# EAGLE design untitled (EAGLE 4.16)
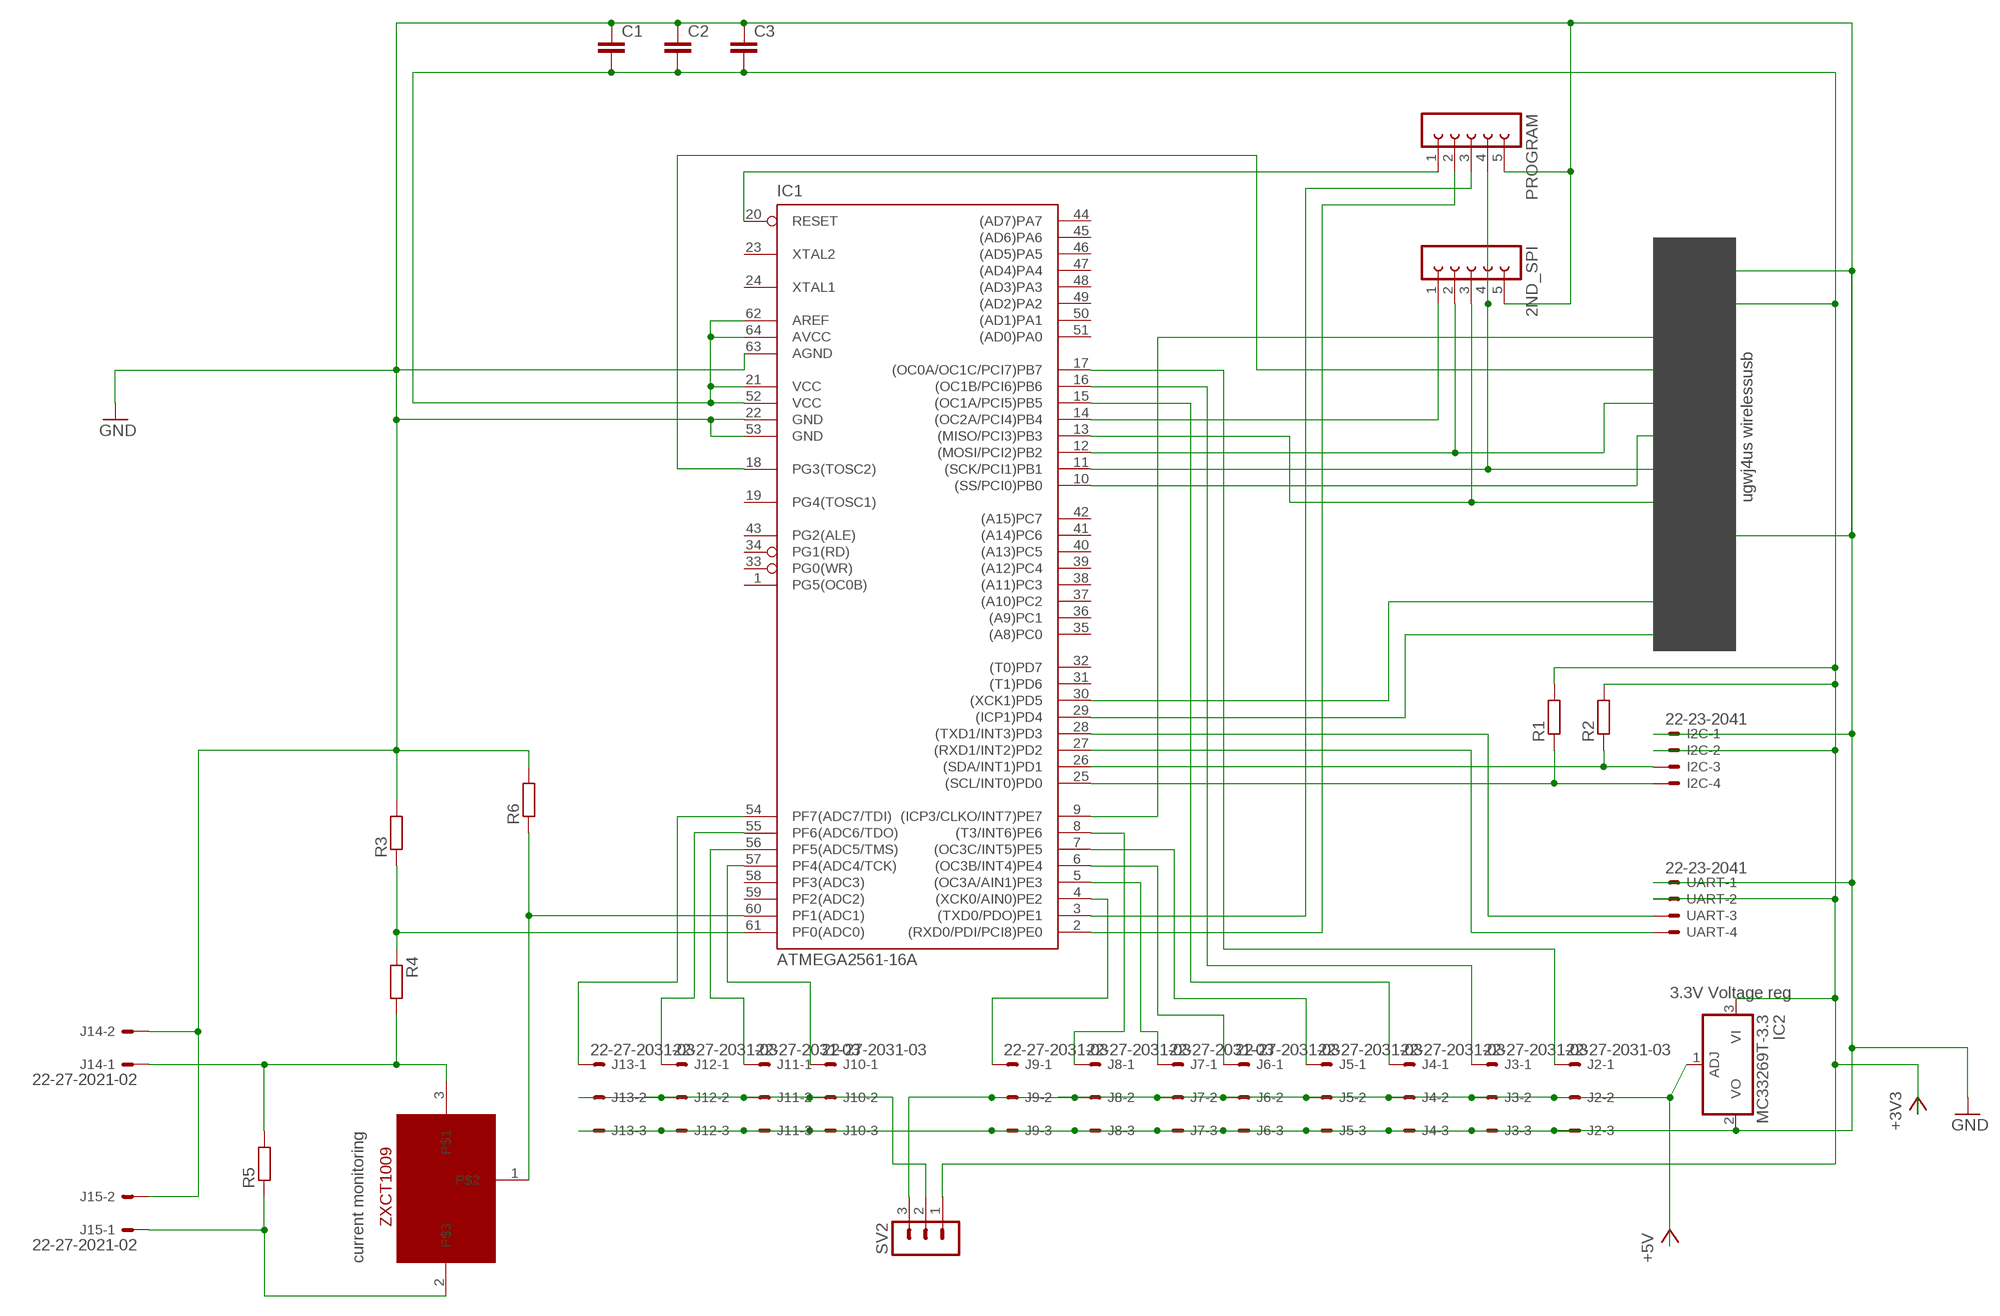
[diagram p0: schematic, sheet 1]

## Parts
2ND_SPI  FE05-1  [FE05-1]
C1  C-EUC0805  [C0805]
C2  C-EUC0805  [C0805]
C3  C-EUC0805  [C0805]
I2C  22-23-2041  [22-23-2041]
IC1  ATMEGA2561-16A  [TQFP64]
IC2  MC33269T-3.3  [TO220V]
J1  J-12-2MM-2X06  [HDR-2MM-2X06]
J2  22-27-2031-03  [6410-03]
J3  22-27-2031-03  [6410-03]
J4  22-27-2031-03  [6410-03]
J5  22-27-2031-03  [6410-03]
J6  22-27-2031-03  [6410-03]
J7  22-27-2031-03  [6410-03]
J8  22-27-2031-03  [6410-03]
J9  22-27-2031-03  [6410-03]
J10  22-27-2031-03  [6410-03]
J11  22-27-2031-03  [6410-03]
J12  22-27-2031-03  [6410-03]
J13  22-27-2031-03  [6410-03]
J14  22-27-2021-02  [6410-02]
J15  22-27-2021-02  [6410-02]
PROGRAM  FE05-1  [FE05-1]
R1  R-EU_M0805  [M0805]
R2  R-EU_M0805  [M0805]
R3  R-EU_M0805  [M0805]
R4  R-EU_M0805  [M0805]
R5  R-EU_R2512  [R2512]
R6  R-EU_M0805  [M0805]
SV2  MA03-1  [MA03-1]
U$1  DLA  [SOT23]
UART  22-23-2041  [22-23-2041]

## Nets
+3V3: C1.2 C2.2 C3.2 I2C.2 IC1.21(VCC) IC1.52(VCC) IC1.62(AREF) IC1.64(AVCC) IC2.3(VI) J1.2 R1.2 R2.2 SV2.1 UART.2
+5V: IC2.1(ADJ) J2.2 J3.2 J4.2 J5.2 J6.2 J7.2 J8.2 J9.2 SV2.3
GND: 2ND_SPI.5 C1.1 C2.1 C3.1 I2C.1 IC1.22(GND) IC1.53(GND) IC1.63(AGND) IC2.2(VO) J1.1 J1.9 J2.3 J3.3 J4.3 J5.3 J6.3 J7.3 J8.3 J9.3 J10.3 J11.3 J12.3 J13.3 J14.2 J15.2 PROGRAM.5 R3.2 R6.2 UART.1
N$1: IC1.3((TXD0/PDO)PE1) PROGRAM.3
N$2: 2ND_SPI.2 IC1.12((MOSI/PCI2)PB2) J1.5
N$3: IC1.9((ICP3/CLKO/INT7)PE7) J1.3
N$4: IC1.18(PG3(TOSC2)) J1.4
N$5: IC1.10((SS/PCI0)PB0) J1.6
N$6: IC1.2((RXD0/PDI/PCI8)PE0) PROGRAM.2
N$7: I2C.3 IC1.26((SDA/INT1)PD1) R2.1
N$8: 2ND_SPI.1 IC1.14((OC2A/PCI4)PB4)
N$9: 2ND_SPI.4 IC1.11((SCK/PCI1)PB1) J1.7 PROGRAM.4
N$10: I2C.4 IC1.25((SCL/INT0)PD0) R1.1
N$11: IC1.5((OC3A/AIN1)PE3) J7.1
N$12: IC1.4((XCK0/AIN0)PE2) J9.1
N$13: IC1.28((TXD1/INT3)PD3) UART.3
N$14: IC1.17((OC0A/OC1C/PCI7)PB7) J2.1
N$15: IC1.16((OC1B/PCI6)PB6) J3.1
N$16: IC1.15((OC1A/PCI5)PB5) J4.1
N$17: IC1.8((T3/INT6)PE6) J8.1
N$18: IC1.7((OC3C/INT5)PE5) J5.1
N$19: IC1.6((OC3B/INT4)PE4) J6.1
N$20: IC1.61(PF0(ADC0)) R3.1 R4.1
N$21: J15.1 R5.1 U$1.2
N$23: IC1.60(PF1(ADC1)) R6.1 U$1.1
N$24: J14.1 R4.2 R5.2 U$1.3
N$26: IC1.29((ICP1)PD4) J1.12
N$27: IC1.30((XCK1)PD5) J1.11
N$28: IC1.57(PF4(ADC4/TCK)) J10.1
N$29: IC1.56(PF5(ADC5/TMS)) J11.1
N$30: J10.2 J11.2 J12.2 J13.2 SV2.2
N$31: IC1.55(PF6(ADC6/TDO)) J12.1
N$32: IC1.54(PF7(ADC7/TDI)) J13.1
N$33: IC1.27((RXD1/INT2)PD2) UART.4
N$35: IC1.20(RESET) PROGRAM.1
N$36: 2ND_SPI.3 IC1.13((MISO/PCI3)PB3) J1.8
Unconnected: IC1.1(PG5(OC0B)) IC1.19(PG4(TOSC1)) IC1.23(XTAL2) IC1.24(XTAL1) IC1.31((T1)PD6) IC1.32((T0)PD7) IC1.33(PG0(WR)) IC1.34(PG1(RD)) IC1.35((A8)PC0) IC1.36((A9)PC1) IC1.37((A10)PC2) IC1.38((A11)PC3) IC1.39((A12)PC4) IC1.40((A13)PC5) IC1.41((A14)PC6) IC1.42((A15)PC7) IC1.43(PG2(ALE)) IC1.44((AD7)PA7) IC1.45((AD6)PA6) IC1.46((AD5)PA5) IC1.47((AD4)PA4) IC1.48((AD3)PA3) IC1.49((AD2)PA2) IC1.50((AD1)PA1) IC1.51((AD0)PA0) IC1.58(PF3(ADC3)) IC1.59(PF2(ADC2)) J1.10

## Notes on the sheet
- ugwj4us wirelessusb
- 3.3V Voltage reg
- current monitoring

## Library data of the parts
2ND_SPI PROGRAM = con-lsta:FE05-1: FEMALE HEADER
C1-C3 = rcl:C-EU: CAPACITOR, European symbol
I2C UART = con-molex:22-23-2041: .100" (2.54mm) Center Header - 4 Pin
IC1 = avr:ATMEGA2561: MICROCONTROLLER 256 Kbytes FLASH 8 Kbytes SRAM 4 Kbytes EEPROM DUAL USART 8-channel 10 bit ADC
IC2 = linear:MC33269?*: Adjustable Output Low Dropout Voltage Regulator 800 mA Source: http://www.onsemi.com/pub/Collateral/MC33269-D.PDF
J1 = con-headers-jp:J-12-: HEADER JACK PINS
J2-J13 = con-molex:22-?-03: CONNECTOR wire to board 2.54 mm (.1 inch) pitch header
J14 J15 = con-molex:22-?-02: CONNECTOR
R1-R6 = rcl:R-EU_: RESISTOR, European symbol
SV2 = con-lstb:MA03-1: PIN HEADER
U$1 = zxct1009:DLA

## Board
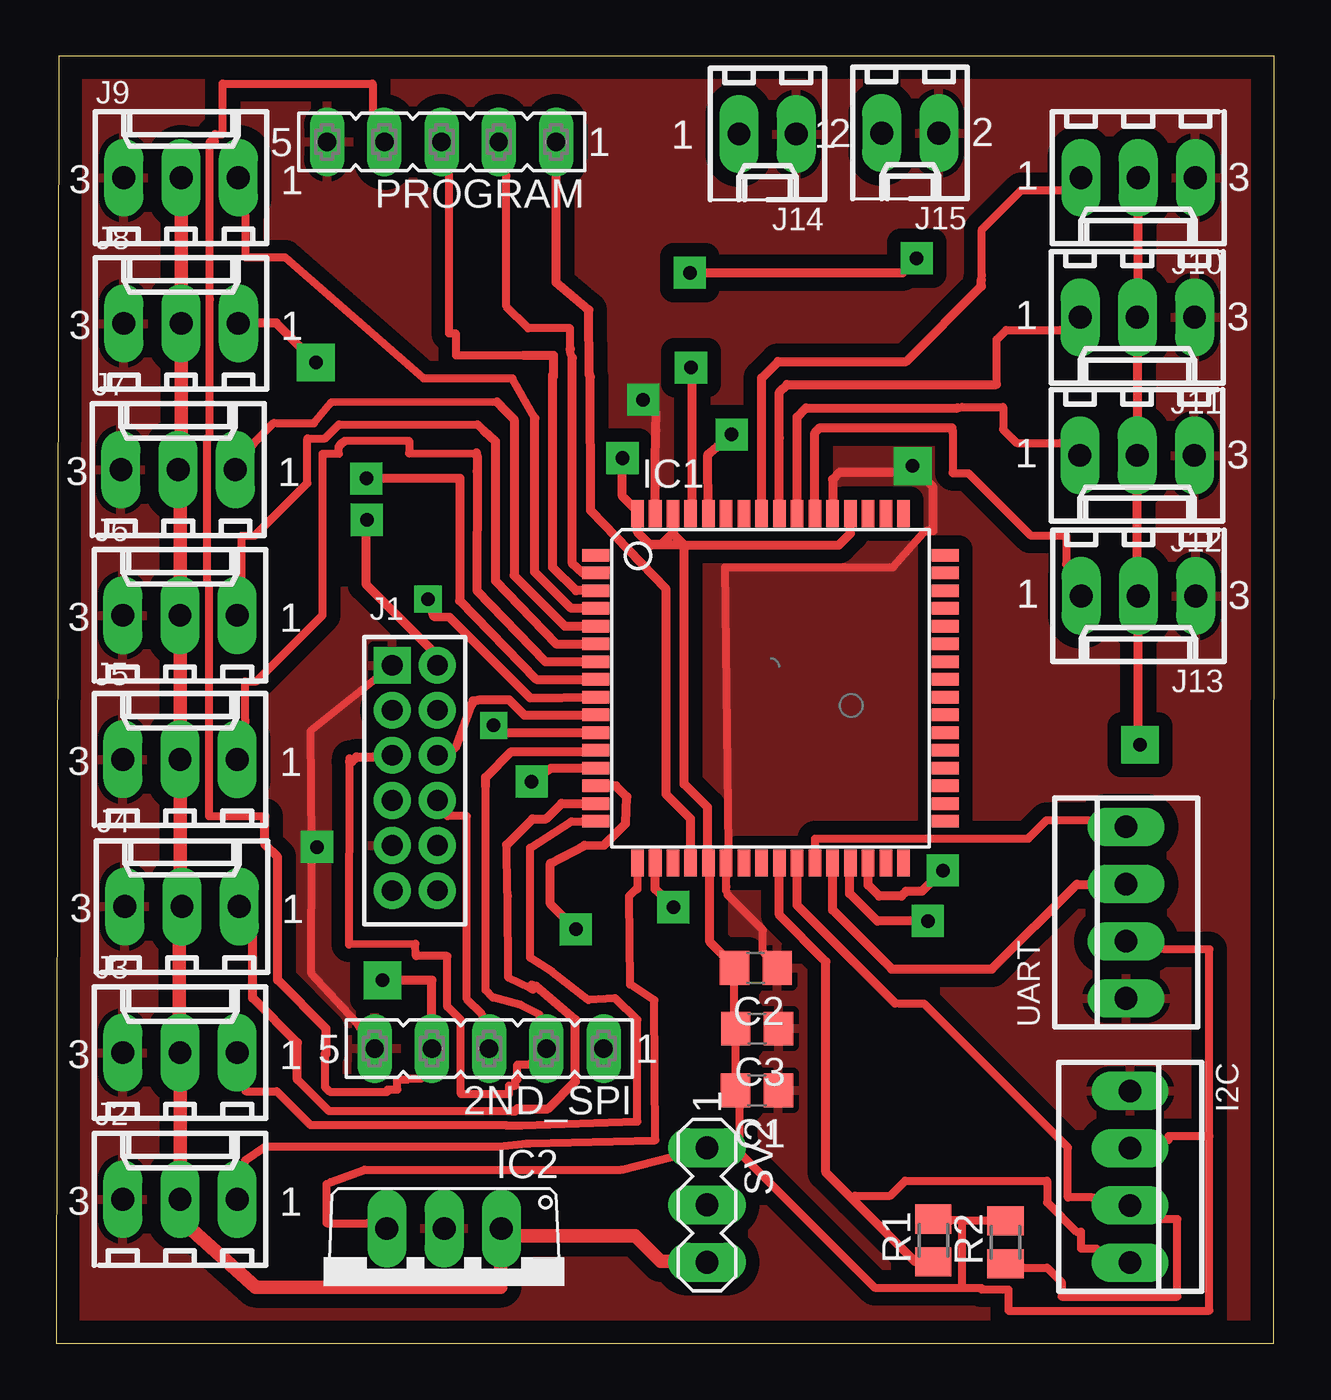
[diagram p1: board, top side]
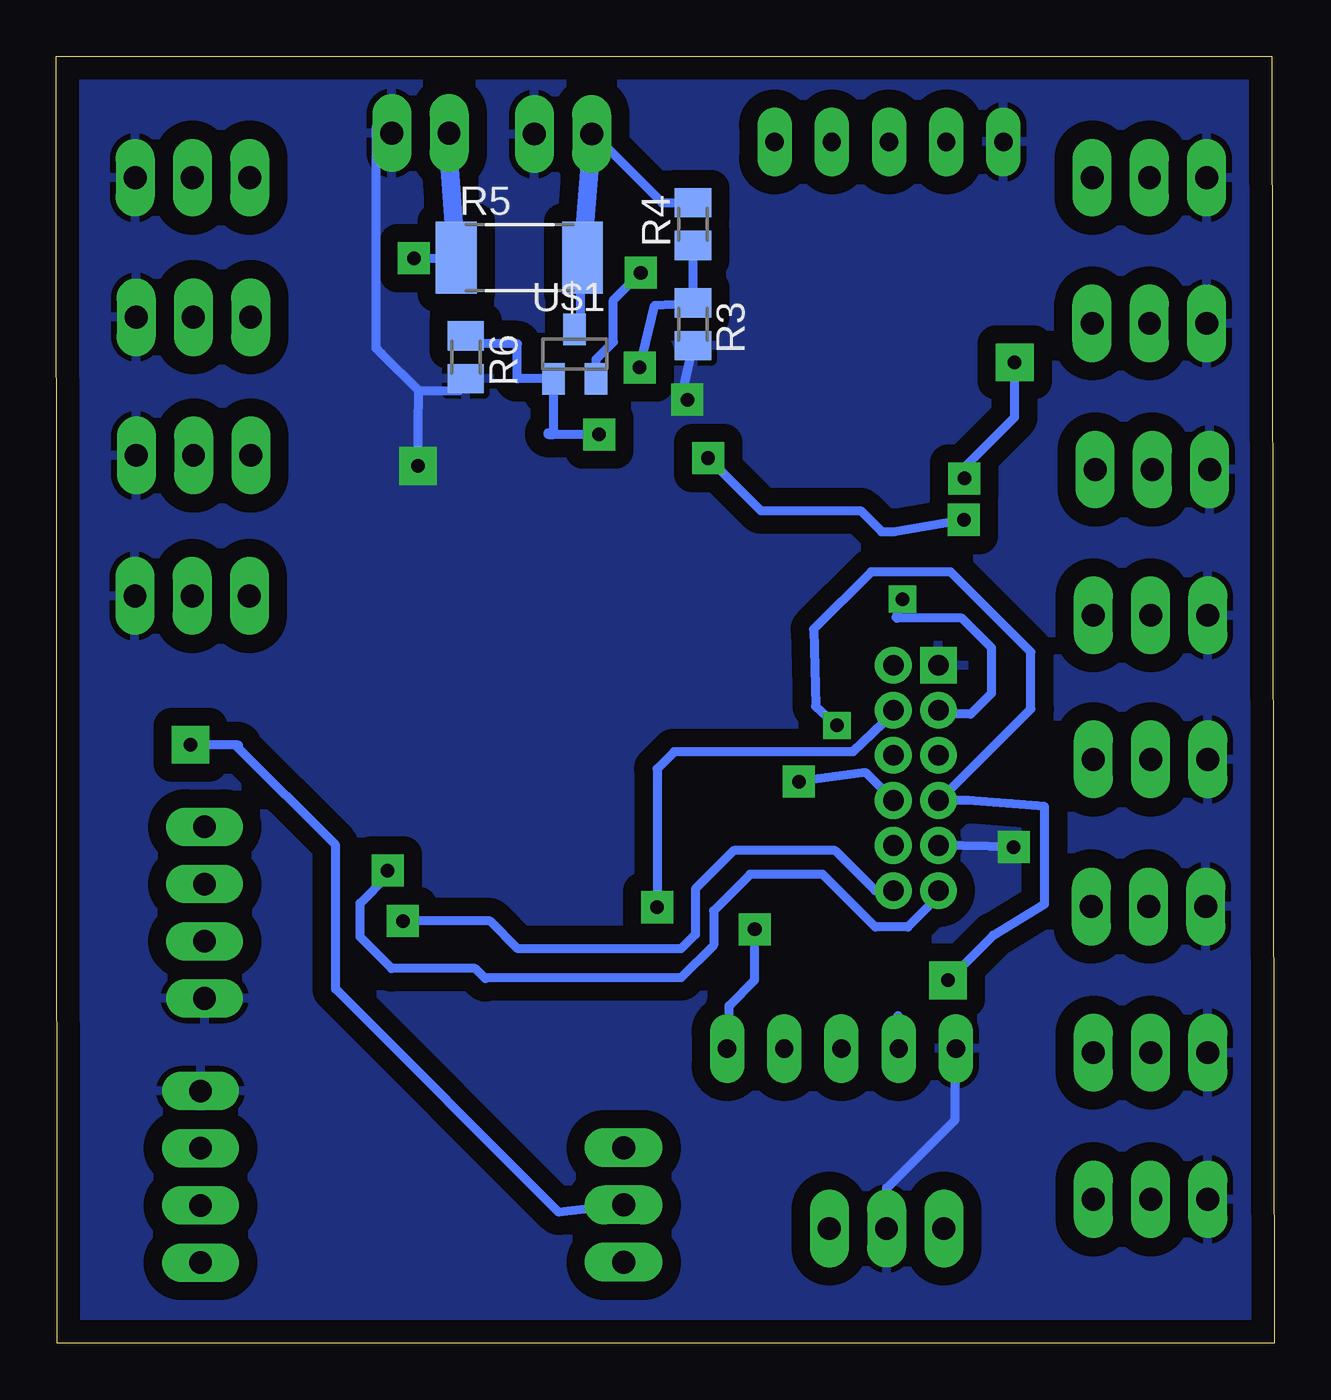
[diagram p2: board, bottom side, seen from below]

Size 54.06 x 57.14 mm. Coordinates in mm from the lower left corner, seen from the top.
Outline: 0,0 54.03,0 54.06,57.14 0.11,57.14 0,0
Copper layers (1*16): Top 0.035mm / dielectric 1.5mm / Bottom 0.035mm
Design rules "default": minimum track width 14mil, minimum drill 24mil, track to track 10mil, track to pad 8mil, pad to pad 8mil, via to via 12mil, smd to smd 8mil, copper to edge 40mil, drill to drill 8mil, minimum pad ring 14mil, minimum via ring 12mil, stop-mask expansion 4mil, vias tented up to drill 0mil, thermal gap 10mil

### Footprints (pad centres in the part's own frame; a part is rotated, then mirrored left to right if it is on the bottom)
FE05-1 = drill 0.813 long: 1 -5.08,0; 2 -2.54,0; 3 0,0; 4 2.54,0; 5 5.08,0
C0805 = smd 1.3 x 1.5: 1 -0.95,0; 2 0.95,0
22-23-2041 = drill 1 long: 1 -3.81,0; 2 -1.27,0; 3 1.27,0; 4 3.81,0
TQFP64 = smd 1.194 x 0.559: 1 -7.76,5.905; 2 -7.76,5.118; 3 -7.76,4.331; 4 -7.76,3.543; 5 -7.76,2.756; 6 -7.76,1.968; 7 -7.76,1.181; 8 -7.76,0.394; 9 -7.76,-0.394; 10 -7.76,-1.181; 11 -7.76,-1.968; 12 -7.76,-2.756; 13 -7.76,-3.543; 14 -7.76,-4.331; 15 -7.76,-5.118; 16 -7.76,-5.905; 33 7.76,-5.905; 34 7.76,-5.118; 35 7.76,-4.331; 36 7.76,-3.543; 37 7.76,-2.756; 38 7.76,-1.968; 39 7.76,-1.181; 40 7.76,-0.394; 41 7.76,0.394; 42 7.76,1.181; 43 7.76,1.968; 44 7.76,2.756; 45 7.76,3.543; 46 7.76,4.331; 47 7.76,5.118; 48 7.76,5.905 | smd 0.559 x 1.194: 17 -5.905,-7.76; 18 -5.118,-7.76; 19 -4.331,-7.76; 20 -3.543,-7.76; 21 -2.756,-7.76; 22 -1.968,-7.76; 23 -1.181,-7.76; 24 -0.394,-7.76; 25 0.394,-7.76; 26 1.181,-7.76; 27 1.968,-7.76; 28 2.756,-7.76; 29 3.543,-7.76; 30 4.331,-7.76; 31 5.118,-7.76; 32 5.905,-7.76; 49 5.905,7.76; 50 5.118,7.76; 51 4.331,7.76; 52 3.543,7.76; 53 2.756,7.76; 54 1.968,7.76; 55 1.181,7.76; 56 0.394,7.76; 57 -0.394,7.76; 58 -1.181,7.76; 59 -1.968,7.76; 60 -2.756,7.76; 61 -3.543,7.76; 62 -4.331,7.76; 63 -5.118,7.76; 64 -5.905,7.76
TO220V = drill 1.016 long: 1 -2.54,-2.54; 2 0,-2.54; 3 2.54,-2.54
HDR-2MM-2X06 = drill 0.914 square: 1 -5,-1 | drill 0.914 round: 2 -5,1; 3 -3,-1; 4 -3,1; 5 -1,-1; 6 -1,1; 7 1,-1; 8 1,1; 9 3,-1; 10 3,1; 11 5,-1; 12 5,1
6410-03 = drill 1.016 long: 1 2.54,0; 2 0,0; 3 -2.54,0
6410-02 = drill 1.016 long: 1 1.27,0; 2 -1.27,0
M0805 = smd 1.3 x 1.6: 1 -0.95,0; 2 0.95,0
R2512 = smd 1.8 x 3.2: 1 -2.8,0; 2 2.8,0
MA03-1 = drill 1.016 long: 1 -2.54,0; 2 0,0; 3 2.54,0
SOT23 = smd 1 x 1.4: 1 -0.95,-1.1; 2 0.95,-1.1; 3 0,1.1

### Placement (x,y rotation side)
2ND_SPI  19.21,13.08 180 top
C1  31.1,11.23 180 top
C2  31.05,16.66 180 top
C3  31.11,13.97 180 top
I2C  47.66,7.39 270 top
IC1  31.7,29.08 0 top
IC2  17.21,2.55 180 top
J1  15.91,25.1 270 top
J2  5.49,6.39 0 top
J3  5.49,12.9 0 top
J4  5.58,19.39 0 top
J5  5.49,25.92 0 top
J6  5.49,32.32 0 top
J7  5.41,38.79 0 top
J8  5.54,45.28 0 top
J9  5.54,51.75 0 top
J10  48.02,51.75 180 top
J11  47.98,45.55 180 top
J12  47.97,39.42 180 top
J13  48.03,33.18 180 top
J14  31.57,53.69 180 top
J15  37.9,53.73 180 top
PROGRAM  17.1,53.34 180 top
R1  38.93,4.56 90 top
R2  42.13,4.48 90 top
R3  25.8,45.24 270 bottom
R4  25.8,49.69 90 bottom
R5  33.51,48.2 0 bottom
R6  35.88,43.78 270 bottom
SV2  28.88,6.14 270 top
U$1  31.05,43.92 0 bottom
UART  47.48,19.12 90 top

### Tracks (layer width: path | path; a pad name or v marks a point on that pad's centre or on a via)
+3V3  (via drill 0.6 pad 1.42)
  Top 0.356: IC2.3 13.82,5.33 12,5.33 12,7.07 12.16,7.15 13.68,7.7 25.08,7.7 SV2.1 28.5,8.67 30.34,8.67 | 51.18,9.19 49.36,9.19 49.36,9.01 I2C.2 | 51.18,9.19 51.18,17.49 49.18,17.49 UART.2 | 40.22,5.45 41.34,5.45 R2.2 | 40.22,5.45 39.72,5.45 R1.2 | C2.2 30.1,14.71 C3.2 30.16,11.97 C1.2 30.34,10.49 30.34,8.67 | 40.22,2.47 36.32,2.47 30.34,8.45 30.34,8.67 | 40.22,2.47 40.22,5.45 | 51.18,9.19 51.18,1.45 42.26,1.45 42.26,2.39 41.06,2.39 41.06,2.45 40.38,2.45 40.22,2.47
  Top 0.406: IC1.52 35.24,35.95 34.72,35.43 27.87,35.43 | 27.87,35.43 27.4,35.9 27.4,35.94 | 27.33,36.84 | 27.33,36.84 IC1.62 | 27.4,35.94 27.4,36.77 27.33,36.84 | 27.4,35.94 27.33,35.94 26.86,35.47 26.35,35.47 25.79,36.03 IC1.64 25.82,36.84 25.86,36.88 25.13,37.61 v25.13,39.3 | 27.87,35.43 26.39,35.43 | 27.87,35.43 27.87,24.83 28.91,23.79 28.91,21.46 29.03,21.34 29.01,21.32 | 29.01,21.32 IC1.21 | J1.2 16.91,30.54 13.74,33.71 13.74,36.49 13.8,36.55 v13.79,36.56 v13.78,36.56 | 30.17,16.66 30.21,16.62 | C2.2 30.17,16.66 | 29.01,21.32 29.01,17.82 30.17,16.66
  Bottom 0.406: v13.78,36.56 16.88,36.03 17.43,36.03 18.36,36.96 22.79,36.96 v25.13,39.3
+5V
  Top 0.406: J7.2 5.41,38.74 5.49,38.66 5.54,38.71 | J6.2 5.54,32.32 5.58,32.36 5.41,32.53 | 5.49,25.73 J5.2 | J4.2 5.58,19.59 5.49,19.68 | J3.2 5.49,12.88 5.58,12.97 | 5.69,6.39 5.66,6.17 | J2.2 5.69,6.39 | 5.69,6.39 5.49,6.59
  Top 0.61: J9.2 J8.2 5.54,38.97 5.38,38.81 J7.2 | J6.2 5.54,32.36 5.49,32.41 5.49,38.66 | J6.2 | 5.4,25.92 5.38,25.9 | J5.2 5.4,25.92 | J6.2 5.5,26.02 5.4,25.92 | 5.49,19.23 5.58,19.32 J4.2 | 5.49,19.23 5.49,25.73 | 5.49,19.23 5.46,19.2 5.46,12.99 5.38,12.91 5.39,12.9 J3.2 | 5.78,6.45 5.72,6.39 J2.2 | 5.49,12.88 5.49,6.74 5.78,6.45 | 5.78,6.45 5.78,5.24 8.85,2.49 19.73,2.49 19.73,4.68 19.81,4.76 19.8,4.77 | 19.8,4.77 IC2.1 | 19.8,4.77 25.69,4.77 26.83,3.63 28.84,3.63 SV2.3
GND  (via drill 0.6 pad 1.42, 0.6 pad 1.68)
  Top 0.356: J1.1 11.3,27.2 11.35,22.14 11.32,16.42 13.3,14.28 2ND_SPI.5 | C2.1 31.36,17.39 31.36,18.35 29.8,19.91 29.73,20.08 29.74,20.27 29.74,20.73 IC1.22 29.84,21.91 29.68,34.46 37.14,34.46 38.5,35.99 38.7,36.08
  Top 0.406: IC1.63 26.58,38.96 26.61,40.53 26.62,41.29 v26.05,41.89 | IC1.53 34.46,38.36 34.76,38.66 37.87,38.66 v38.01,38.95 38.11,38.85 38.11,38.81 38.12,38.81 38.92,38.01 38.92,36.08 38.7,36.08 | 11.35,22.14 11.15,22.02 11.18,22.07 v11.57,22.03
  Bottom 0.406: R3.2 25.78,44.29 26.24,42.35 v26.05,41.89 | v38.01,38.95 37.98,42.29 | 37.98,42.29 39.63,43.94 39.86,44.18 39.86,53.97 J15.2 | R6.2 36.18,42.83 36.18,42.29 37.98,42.29 | IC2.2 17.21,6.88 14.17,9.92 14.17,13.07 14.16,13.08 2ND_SPI.5 | v11.57,22.03 J1.9
  pour Bottom (isolate 0.813): 0.46,56.97 53.59,56.97 53.59,0.4 0.3,0.4 0.3,0.56
  pour Top (isolate 0.61): 0.54,56.81 0.54,0.64 53.75,0.64 53.75,56.65 53.51,56.65
N$1
  Top 0.356: 20.74,43.86 17.74,43.86 17.74,44.81 17.72,44.83 17.44,44.83 17.44,51.85 PROGRAM.3
  Top 0.406: IC1.3 23.07,33.41 22.03,34.45 22.03,42.93 | 22.03,42.93 22.03,42.97 | 22.03,42.93 22.07,42.93 22.07,43.86 20.74,43.86
N$2
  Top 0.356: 19.05,24.74 19.05,15.68 19.38,15.35 20.6,15.03 21.44,14.59 2ND_SPI.2 21,12.37 20.46,12.37 20.46,11.71 20.38,11.71 20.38,11.43 20.1,11.43 20.1,11.07 17.96,11.07 17.96,14.35 17.38,14.93 17.36,14.93 17.36,17.19 15.96,17.19 15.94,17.73 13,17.7 13.02,25.82 13.02,25.98 | 14.1,26.03 J1.5
  Top 0.406: 13.12,25.82 | 13.02,25.82 13.12,25.82 | 14.1,26.03 13.33,26.03 13.12,25.82 | 19.05,24.74 19.05,25.12 20.2,26.27 23.99,26.27 | 23.96,26.34 IC1.12 23.99,26.27 | 23.99,26.27 24.02,26.27
N$3  (via drill 0.6 pad 0.81)
  Top 0.406: IC1.9 21.03,28.66 17.45,32.24 16.76,32.27 v16.5,33.04
  Bottom 0.406: J1.3 14.91,27.95 14.93,27.93 13.48,27.93 12.55,28.86 12.55,30.87 13.87,32.19 16.74,32.19 16.79,32.24 v16.5,33.04
N$4  (via drill 0.6 pad 1.42)
  Top 0.356: 26.58,21.91 IC1.18
  Top 0.406: 26.58,21.91 26.58,20.17 v27.39,19.36
  Bottom 0.406: J1.4 16.91,27.97 18.7,26.26 26.64,26.26 26.64,26.25 27.39,25.5 v27.39,19.36
N$5
  Top 0.356: 18.44,28.37 17.72,26.43 J1.6 | 23.36,27.89 IC1.10
  Top 0.406: 23.36,27.89 20.78,27.89 20.09,28.58 18.8,28.58 18.5,28.52 18.44,28.37
N$6
  Top 0.356: IC1.2 24.52,34.31 | 22.81,44.12 22.82,43.95 22.91,43.76 | 22.83,44.14 22.8,44.33 22.8,45.07 20.94,45.07 19.98,46.03 19.98,51.83 19.96,51.83 PROGRAM.2
  Top 0.406: IC1.2 23.36,34.2 22.91,34.61 22.91,43.76 | 22.81,44.12 22.83,44.14
N$7
  Top 0.356: R2.1 42.92,3.35 43.98,3.35 44.62,2.71 44.62,2.07 49.76,2.07 49.76,5.51 49.1,5.51 I2C.3 45.96,6.47 44.9,6.47 44.9,8.69 38.52,15.07 37.42,15.07 37.23,15.09
  Top 0.406: IC1.26 32.88,19.44 37.23,15.09
N$8  (via drill 0.6 pad 1.42)
  Top 0.406: IC1.14 24.83,24.75 25.32,24.26 25.27,23.07 24.32,22.12 23.45,22.11 21.93,21.31 21.93,19.51 v23.06,18.38
  Bottom 0.406: 24.28,13.28 24.29,13.1 2ND_SPI.1 24.2,13.17 24.2,14.98 23.06,16.12 v23.06,18.38
N$9  (via drill 0.6 pad 0.81, 0.6 pad 1.68)
  Top 0.356: 9.26,23.39 6.78,23.39 6.78,33.69 6.72,33.75 6.7,33.75 6.7,40.19 6.78,40.27 6.8,40.27 6.8,46.33 6.82,46.35 6.82,53.35 7.04,53.35 7.04,53.69 7.38,53.69 7.38,55.93 14.04,55.93 14.04,54.65 PROGRAM.4 | 11.92,12.83 11.92,11.37 11.94,11.37 12.14,11.17 14.7,11.17 14.7,11.27 15.14,11.27 15.14,11.71 15.58,11.71 15.58,11.75 16.18,11.75 2ND_SPI.4
  Top 0.406: v14.48,16.11 16.67,16.11 2ND_SPI.4 | 9.26,23.39 9.26,22.14 9.82,21.58 9.82,16.12 11.98,13.96 11.98,12.85 11.96,12.83 11.92,12.83 | 19.67,27.41 v19.41,27.43 19.97,27.11 23.87,27.11 IC1.11
  Bottom 0.406: 2ND_SPI.4 16.67,13.12 16.71,13.16 16.71,14.39 | 16.71,14.39 16.71,14.55 | 16.71,14.39 16.72,14.39 | v14.48,16.11 12.48,18.11 10.19,19.5 10.19,23.83 13.6,24.1 J1.7 14.86,24.1 10.8,28.16 10.8,30.68 14.37,34.25 17.9,34.25 20.45,31.7 20.36,28.28 v19.41,27.43
N$10
  Top 0.356: I2C.4 46.18,4.15 46.18,4.21 45.48,4.21 45.48,4.95 45.28,4.95 43.98,6.25 43.98,7.21 37.68,7.21 37.02,6.55 35.46,6.55 35.33,6.41
  Top 0.406: IC1.25 32.09,19.01 34.16,16.94 34.16,7.58 35.33,6.41 38.11,3.63 39,3.63 38.98,3.61 R1.1
N$11
  Top 0.356: J7.1 8.8,40.01 9.66,40.87 9.82,40.85 11.43,40.85 12.21,41.78 19.55,41.8
  Top 0.406: IC1.5 22.57,31.84 20.32,34.09 20.32,41.02 19.9,41.44 19.55,41.8
N$12
  Top 0.356: 21.24,41.07 20.24,42.83 16.3,42.83 10.16,48.21 8.4,48.21 8.4,50.03 J9.1
  Top 0.406: IC1.4 22.86,32.62 21.23,34.25 21.24,34.26 21.24,41.07
N$13
  Top 0.406: IC1.28 34.46,19.23 37.08,16.61 41.53,16.61 45.3,20.38 47.43,20.38 47.46,20.35 47.48,20.37 UART.3
N$14
  Top 0.356: IC1.17 25.8,20.73 25.8,20.15 25.72,20.15 25.42,19.85 25.47,15.93 26.54,15.23 26.59,9.01 21,8.87 20.88,8.87 19.67,8.73 19.65,8.74 9.29,8.74 8.38,8.11 J2.1
N$15
  Top 0.356: IC1.16 23.36,23.17 22.86,23.17 21.03,21.99 21.03,17.11 22.01,16.49 23.61,15.24 24.8,15.32 25.79,14.36 25.79,9.84 20.65,9.67 19.98,9.67 19.96,9.69 11.28,9.69 9.78,11.19 8.4,11.19 J3.1
N$16
  Top 0.356: 21.03,15.76 21.16,15.69 | 21.03,15.76 20.06,16.23 20.04,19.85 20.03,20.01 20.01,20.04 19.99,22.11 | 20.24,10.31 12.1,10.31 10.7,11.71 | J4.1 8.66,17.85 | 21.03,15.76 21.1,15.91 21.3,15.85
  Top 0.406: 21.3,15.85 23.04,14.36 23.04,11.62 21.83,10.41 20.46,10.41 20.36,10.31 20.24,10.31 | 10.7,11.71 10.7,13.34 8.71,15.33 8.71,18.69 8.07,19.33 J4.1 | 19.99,22.11 19.99,22.13 21.14,23.28 21.74,23.28 22.43,23.97 23.87,23.97 23.9,23.94 23.92,23.96 IC1.15
N$17  (via drill 0.6 pad 1.42, 0.6 pad 1.68)
  Top 0.406: IC1.8 21.31,29.47 17.9,32.97 17.91,38.41 v13.75,38.41 v13.76,38.4 | v8.13,45.3 9.77,45.3 v11.52,43.55
  Bottom 0.406: v8.13,45.3 8.11,45.28 J8.1 | v13.76,38.4 13.77,38.87 11.52,41.12 v11.52,43.55
N$18
  Top 0.356: J5.1 8.4,27.63 8.38,27.79 8.38,29.39 8.88,29.39 11.82,32.33 11.82,39.49 12.54,39.49 12.54,39.85 12.6,39.85 12.6,39.91 12.66,39.91 12.66,39.97 12.72,39.97 12.72,40.03 12.78,40.03 12.78,40.07 15.66,40.07 15.66,39.51 18.64,39.53
  Top 0.406: IC1.7 21.71,30.26 18.67,33.43 18.68,38.71 18.68,39.4 18.62,39.46 18.64,39.48 18.64,39.53
N$19
  Top 0.356: 19,40.49 18.7,40.79 12.54,40.79 11.92,40.17 11.14,40.17 11.14,38.19 8.8,35.85 8.22,35.85 8.22,34.03 J6.1
  Top 0.406: IC1.6 22.18,31.05 19.49,33.86 19.49,40.05 18.98,40.52 19,40.49
N$20  (via drill 0.6 pad 1.42)
  Top 0.406: v28.17,43.32 28.23,43.17 28.23,37 28.16,36.93 IC1.61
  Bottom 0.406: R4.1 25.8,46.37 25.86,46.31 25.8,46.25 R3.1 27.49,46.09 v28.17,43.32
N$21  (via drill 0.6 pad 1.42)
  Top 0.406: v28.12,47.53 37.55,47.53 v38.19,48.17
  Bottom 0.406: U$1.2 30.1,43.69 29.33,44.46 29.33,46.32 v28.12,47.53 | R5.1 36.45,48.2 36.5,48.25 36.58,48.17 v38.19,48.17
  Bottom 0.813: J15.1 36.7,53.65 R5.1
N$23  (via drill 0.6 pad 1.42)
  Top 0.406: IC1.60 28.92,39.46 v29.97,40.35
  Bottom 0.406: R6.1 35.94,44.73 35.94,44.38 33.6,44.38 33.6,42.82 U$1.1 31.99,40.35 32.23,40.35 | v29.97,40.35 32.23,40.35 | 32.23,40.35 32.23,40.43
N$24
  Bottom 0.406: 30.04,53.63 30.1,53.57 29.92,53.39 | R4.2 27.17,50.64 29.92,53.39 | 29.98,53.39 29.98,53.33 | 29.98,53.39 29.92,53.39 | J14.1 29.98,53.69 29.98,53.39 | R5.2 30.78,48.2 30.78,45.02 U$1.3
  Bottom 0.813: J14.1 30.27,53.65 R5.2
N$26  (via drill 0.6 pad 1.42)
  Top 0.406: IC1.29 35.24,21.27 35.29,21.22 35.21,21.14 35.21,19.97 36.44,18.74 v38.68,18.74
  Bottom 0.406: J1.12 17.72,20.1 19.49,21.87 24,21.87 25.7,20.17 25.7,18.15 26.34,17.51 33.57,17.51 34.8,18.74 v38.68,18.74
N$27  (via drill 0.6 pad 1.42)
  Top 0.406: 36.03,21.39 36.1,21.46 | 36.03,21.39 IC1.30 36.03,20.34 36.52,19.85 37.51,19.85 37.72,20.06 38.42,20.06 v39.35,20.99 | 36.03,21.39 36.02,21.38
  Bottom 0.406: J1.11 14.91,19.83 16.26,18.48 17.71,18.48 20.05,20.82 23.27,20.82 24.89,19.2 24.89,17.67 26.34,16.22 34.97,16.22 35.01,16.18 35.47,16.64 39.18,16.64 40.58,18.04 40.58,19.53 39.35,20.76 v39.35,20.99
N$28
  Top 0.356: J10.1 44.62,51.19 42.82,51.19 41.08,49.45 41.08,47.41 41.06,47.22
  Top 0.406: IC1.57 31.31,40 | 31.31,40 | 31.31,40 31.31,42.86 32.04,43.59 37.72,43.59 41.06,46.93 41.06,47.22
N$29
  Top 0.356: J11.1 44.58,44.99 42.16,44.99 41.74,44.57 41.74,42.77 41.72,42.57
  Top 0.406: 32.09,40.19 IC1.56 32.09,42.22 32.44,42.57 41.72,42.57
N$30  (via drill 0.6 pad 1.68)
  Top 0.406: J11.2 48.03,45.59 48.02,45.6 J10.2 | J11.2 | J11.2 47.99,39.58 48.11,39.46 48.07,39.42 J12.2 47.97,33.22 48.03,33.16 J13.2 48.03,26.54 48.1,26.47 | 48.1,26.47 48.19,26.38 | v48.1,26.57 48.1,26.47
  Bottom 0.406: 46.05,26.56 46.05,26.49 | 46.05,26.56 45.98,26.56 | 46.09,26.57 46.05,26.57 46.05,26.56 | 46.09,26.57 v48.1,26.57 | SV2.2 31.75,5.82 41.66,15.73 41.66,22.12 46.09,26.55 46.09,26.57
N$31
  Top 0.356: J12.1 44.58,39.97 42.62,39.97 42.02,40.57 42.02,41.57 40.2,41.57 40.01,41.52
  Top 0.406: IC1.55 32.88,41.13 33.27,41.52 40.01,41.52
N$32
  Top 0.356: J13.1 44.82,34.59 44.82,35.87 43.24,35.87 40.48,38.63 39.8,38.63 39.78,38.65 39.78,40.45 39.76,40.65
  Top 0.406: IC1.54 33.67,40.43 33.89,40.65 39.76,40.65
N$33
  Top 0.356: IC1.27 33.68,21.91 33.68,22.41 43.14,22.41 43.96,23.23 45.78,23.23 UART.4
N$35
  Top 0.356: 23.65,43.08 23.66,43.09 23.7,42.9
  Top 0.406: PROGRAM.1 22.18,47.09 23.64,45.87 23.65,43.08 23.65,43.02 | IC1.20 28.16,23.28 27.07,24.37 27.07,33.48 23.71,36.98 23.7,42.9
N$36  (via drill 0.6 pad 1.42)
  Top 0.356: 2ND_SPI.3 18.9,14.59 18.22,15.27 18.22,23.41 17.36,23.41 J1.8
  Top 0.406: IC1.13 21.96,25.54 v21.1,24.94
  Bottom 0.406: J1.8 18.14,25.34 v21.1,24.94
